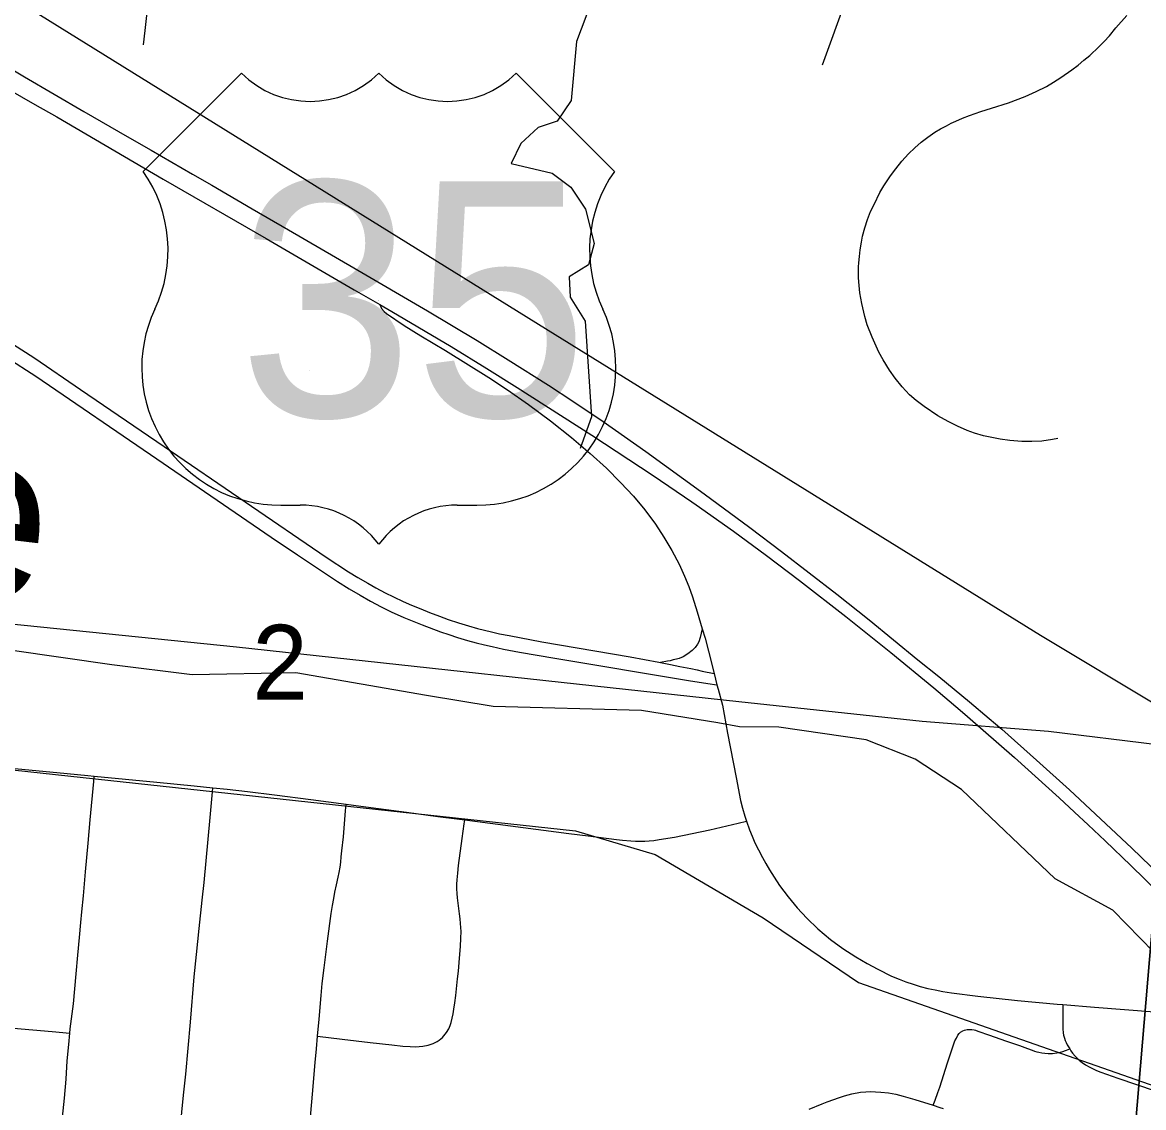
# Model space of a CAD drawing. Extents: x 0 to 34, y 0 to 22.
# Drawn here: x 5.11 to 5.737, y 17.523 to 18.131 of the extents above; entities that cross this region are included whole.
import ezdxf

# ---------------------------------------------------------------- set-up
doc = ezdxf.new("R2010")
doc.units = 0
for name, color, linetype in [('GM_X_City_Street', 7, 'Continuous'), ('GM_X_Corporation', 7, 'Continuous'), ('GM_X_Interchange_Ramps', 7, 'Continuous'), ('GM_X_Minor_River', 7, 'Continuous'), ('GM_X_Minor_River_Text', 7, 'Continuous'), ('GM_X_Rail_Line', 7, 'Continuous'), ('GM_X_Section_Text', 7, 'Continuous'), ('GM_X_State_Route', 7, 'Continuous'), ('GM_X_Township_Road', 7, 'Continuous'), ('GM_X_US_Location', 7, 'Continuous'), ('GM_X_US_Route', 7, 'Continuous'), ('GM_X_US_Shield', 7, 'Continuous')]:
    doc.layers.add(name, color=color, linetype=linetype)

msp = doc.modelspace()

# ---------------------------------------------------------------- linework, layer by layer
at = {"layer": 'GM_X_City_Street'}
for points in [[(5.55739, 18.1068), (5.57104, 18.14451), (5.57768, 18.1645), (5.5839, 18.18399), (5.58488, 18.1876), (5.58576, 18.19118), (5.58681, 18.19643), (5.58746, 18.20021), (5.5882, 18.20466), (5.58873, 18.20758), (5.58942, 18.21067), (5.59154, 18.21843), (5.59321, 18.22309), (5.5966, 18.23108), (5.60566, 18.25239), (5.60637, 18.25407)], [(5.1774, 18.11801), (5.17828, 18.126), (5.17939, 18.13614)], [(5.68919, 17.89762), (5.68616, 17.89706), (5.68007, 17.89623), (5.67456, 17.89593), (5.66903, 17.89602), (5.66228, 17.89655), (5.65679, 17.89733), (5.65222, 17.89821), (5.64758, 17.89914), (5.6424, 17.90065), (5.6384, 17.90213), (5.633, 17.90451), (5.62776, 17.90713), (5.62186, 17.91037), (5.61421, 17.91561), (5.60981, 17.91895), (5.60615, 17.92219), (5.60197, 17.92665), (5.59808, 17.93141), (5.59488, 17.93593), (5.5913, 17.94168), (5.58897, 17.946), (5.58512, 17.95442), (5.58248, 17.96133), (5.58101, 17.96601), (5.57935, 17.97321), (5.57837, 17.97928), (5.57767, 17.98537), (5.57753, 17.98776), (5.57747, 17.9912), (5.57757, 17.99368), (5.57773, 17.996), (5.57814, 17.99952), (5.57855, 18.00324), (5.57922, 18.00753), (5.57986, 18.01087), (5.58104, 18.0156), (5.58258, 18.02029), (5.58434, 18.02473), (5.58623, 18.02874), (5.5895, 18.03536), (5.59167, 18.03905), (5.59546, 18.04466), (5.59836, 18.04863), (5.60182, 18.05291), (5.60552, 18.05699), (5.60908, 18.06048), (5.61265, 18.06353), (5.61637, 18.06632), (5.62035, 18.06911), (5.62339, 18.07097), (5.6268, 18.07273), (5.62949, 18.07417), (5.63197, 18.07531), (5.63569, 18.07696), (5.63965, 18.07842), (5.64605, 18.08072), (5.65194, 18.08265), (5.66147, 18.08561), (5.67077, 18.0891), (5.67707, 18.09189), (5.6827, 18.09478), (5.68672, 18.09709), (5.69071, 18.09969), (5.69686, 18.10404), (5.70044, 18.10677), (5.70368, 18.1094), (5.70702, 18.11214), (5.7121, 18.1169), (5.71499, 18.11984), (5.71794, 18.1231), (5.72166, 18.12754), (5.72776, 18.13449)], [(5.13066, 17.50541), (5.13307, 17.52823), (5.13399, 17.53896), (5.13467, 17.54919), (5.13547, 17.55832), (5.13614, 17.56476), (5.1364, 17.56714), (5.13813, 17.58107), (5.13973, 17.59784), (5.14053, 17.60839), (5.14145, 17.61826), (5.14231, 17.62671), (5.14287, 17.63269), (5.14368, 17.64163), (5.14484, 17.65507), (5.14633, 17.6711), (5.14756, 17.68411), (5.14947, 17.70564), (5.14973, 17.70857)], [(5.19791, 17.51086), (5.19979, 17.53001), (5.20099, 17.54174), (5.2036, 17.57078), (5.20569, 17.59618), (5.20697, 17.60869), (5.20849, 17.62328), (5.21026, 17.63923), (5.21134, 17.64914), (5.21466, 17.6855), (5.21603, 17.69975), (5.21625, 17.70212)], [(5.27004, 17.50932), (5.2719, 17.5306), (5.27344, 17.5483), (5.27412, 17.55596), (5.27473, 17.56302), (5.27559, 17.57254), (5.27677, 17.58586), (5.27744, 17.59252), (5.27843, 17.60122), (5.28043, 17.61625), (5.28248, 17.63165), (5.28318, 17.63625), (5.28386, 17.64014), (5.28453, 17.64359), (5.28546, 17.64766), (5.28639, 17.65198), (5.28688, 17.65469), (5.28737, 17.65766), (5.2878, 17.66049), (5.28805, 17.66339), (5.28836, 17.66684), (5.28922, 17.67455), (5.29046, 17.68911), (5.29078, 17.69293)], [(5.27473, 17.56302), (5.28862, 17.56138), (5.30421, 17.55954), (5.31633, 17.55811), (5.32247, 17.55745), (5.32653, 17.55715), (5.32932, 17.55706), (5.33163, 17.55715), (5.33367, 17.55733), (5.33659, 17.55795), (5.33951, 17.55895), (5.34171, 17.56007), (5.34285, 17.56079), (5.34374, 17.56147), (5.34476, 17.56234), (5.34552, 17.56316), (5.34702, 17.56505), (5.34817, 17.56718), (5.34893, 17.56895), (5.34953, 17.57072), (5.35017, 17.57316), (5.3507, 17.57556), (5.35114, 17.57809), (5.35163, 17.58168), (5.35213, 17.58581), (5.3526, 17.58949), (5.35318, 17.59517), (5.35367, 17.59942), (5.35425, 17.60674), (5.35478, 17.61317), (5.35505, 17.61796), (5.35513, 17.62155), (5.35505, 17.62395), (5.35487, 17.62608), (5.35461, 17.62865), (5.35425, 17.63144), (5.3531, 17.64049), (5.35287, 17.64289), (5.35274, 17.64546), (5.35274, 17.64803), (5.35288, 17.65054), (5.35323, 17.65433), (5.35374, 17.65857), (5.35574, 17.67363), (5.35686, 17.68198), (5.35714, 17.6841)], [(5.69187, 17.58071), (5.69187, 17.57035), (5.69187, 17.56717), (5.69211, 17.56486), (5.69231, 17.56364), (5.69275, 17.56194), (5.69321, 17.56052), (5.69371, 17.55939), (5.6943, 17.55818), (5.69573, 17.55586), (5.69632, 17.55489), (5.69735, 17.55355), (5.69878, 17.5519), (5.69977, 17.55091), (5.70108, 17.54963), (5.70278, 17.54821), (5.70467, 17.54695), (5.70661, 17.5458), (5.70858, 17.54483), (5.71076, 17.54388), (5.71324, 17.54292), (5.72262, 17.53945), (5.76446, 17.52529)], [(5.0706, 17.57041), (5.08086, 17.56953), (5.10466, 17.56747), (5.12626, 17.56561), (5.13614, 17.56476)], [(5.61941, 17.52437), (5.62042, 17.52721), (5.62194, 17.53153), (5.623, 17.53453), (5.62739, 17.54809), (5.63087, 17.55866), (5.63154, 17.56044), (5.6323, 17.56198), (5.63319, 17.56357), (5.63393, 17.56448), (5.6347, 17.56519), (5.63602, 17.56603), (5.63678, 17.56635), (5.63757, 17.56658), (5.63837, 17.5667), (5.63921, 17.56678), (5.64019, 17.56676), (5.64096, 17.5667), (5.64224, 17.5665), (5.64298, 17.56629), (5.6444, 17.56587), (5.65079, 17.56363), (5.6599, 17.56046), (5.66771, 17.55775), (5.67209, 17.55615), (5.67479, 17.55514), (5.67599, 17.55471), (5.67729, 17.55433), (5.67856, 17.55399), (5.68007, 17.55373), (5.68186, 17.55351), (5.68367, 17.55337), (5.68604, 17.55337), (5.6886, 17.55365), (5.69143, 17.55433), (5.69398, 17.55515), (5.69573, 17.55586)], [(5.54988, 17.52211), (5.55725, 17.52522), (5.56009, 17.52631), (5.56684, 17.52875), (5.56971, 17.5297), (5.57381, 17.5308), (5.57859, 17.53164), (5.58161, 17.53194), (5.58402, 17.53201), (5.58706, 17.53194), (5.59009, 17.53172), (5.59427, 17.53124), (5.5984, 17.53049), (5.60254, 17.52949), (5.60903, 17.5276), (5.61941, 17.52437), (5.62309, 17.52316), (5.62499, 17.52246)]]:
    msp.add_lwpolyline(points, dxfattribs=at)
at = {"layer": 'GM_X_Corporation'}
for points in [[(4.80587, 18.33893), (5.79402, 18.23883), (5.70874, 17.23111), (4.7096, 17.33101)], [(5.79402, 18.23883), (6.80258, 18.13648), (6.71605, 17.12273), (5.70874, 17.23111)]]:
    msp.add_lwpolyline(points, close=True, dxfattribs=at)
at = {"layer": 'GM_X_Interchange_Ramps'}
for points in [[(5.30961, 17.97268), (5.31059, 17.9704), (5.31204, 17.96871), (5.3134, 17.96759), (5.32317, 17.96095), (5.33257, 17.95516), (5.34646, 17.94686), (5.3707, 17.93176), (5.38108, 17.92493), (5.39279, 17.91676), (5.40523, 17.90747), (5.41689, 17.89819), (5.42729, 17.88933), (5.43646, 17.88095), (5.44441, 17.8731), (5.45159, 17.86536), (5.45795, 17.85773), (5.46386, 17.84974), (5.46865, 17.84249), (5.47309, 17.83501), (5.47713, 17.82732), (5.48023, 17.82054), (5.48253, 17.81478), (5.48462, 17.80894), (5.48721, 17.80064), (5.49011, 17.7911), (5.49172, 17.78578), (5.4935, 17.77855), (5.49684, 17.76599)], [(5.49011, 17.7911), (5.48901, 17.78618), (5.48824, 17.78384), (5.48749, 17.78242), (5.48616, 17.78069), (5.4845, 17.77899), (5.4821, 17.77707), (5.47948, 17.77549), (5.47722, 17.77455), (5.47562, 17.77403), (5.47388, 17.77365), (5.47218, 17.77323), (5.47058, 17.77295), (5.46674, 17.77227)]]:
    msp.add_lwpolyline(points, dxfattribs=at)
at = {"layer": 'GM_X_Minor_River'}
for points in [[(5.42804, 18.14215), (5.41965, 18.11992), (5.41675, 18.08695), (5.40894, 18.07535), (5.39825, 18.07178), (5.3886, 18.06288), (5.38307, 18.05161), (5.40611, 18.04616), (5.41658, 18.03834), (5.42469, 18.026), (5.42964, 18.0069), (5.42637, 17.99482), (5.41563, 17.98822), (5.41617, 17.97681), (5.42464, 17.96334), (5.42817, 17.90971), (5.42176, 17.892)], [(5.75044, 17.60215), (5.71994, 17.63359), (5.68764, 17.65102), (5.63511, 17.70118), (5.60926, 17.71808), (5.58177, 17.72894), (5.53297, 17.7361), (5.51097, 17.7362), (5.49888, 17.73837), (5.45614, 17.74539), (5.37311, 17.7476), (5.33567, 17.75374), (5.2627, 17.76636), (5.20464, 17.76536), (5.1596, 17.77091), (5.04648, 17.78707)]]:
    msp.add_lwpolyline(points, dxfattribs=at)
at = {"layer": 'GM_X_Rail_Line'}
for points in [[(3.83258, 18.78915), (4.04668, 18.71724), (4.20013, 18.66068), (4.27929, 18.62258), (4.42905, 18.54243), (4.65516, 18.4157), (4.85706, 18.2978), (5.4078, 17.95591), (5.67948, 17.78757), (5.87786, 17.66832)], [(3.75111, 17.91984), (4.13437, 17.89482), (4.75572, 17.82927), (5.22932, 17.78106), (5.51048, 17.75031), (5.61322, 17.7394), (5.68379, 17.7337), (5.74481, 17.72625), (5.77844, 17.71835), (5.81904, 17.69829), (5.87786, 17.66832)], [(3.70448, 17.42229), (3.8238, 17.40968), (4.1793, 17.59433), (4.21884, 17.60563), (4.53197, 17.66904), (4.631, 17.71273), (4.67602, 17.72967), (4.74678, 17.74703), (4.82147, 17.74282), (5.41919, 17.67801), (5.46375, 17.66473), (5.52417, 17.62929), (5.5775, 17.59308), (5.86559, 17.49221), (5.95124, 17.46244), (5.99921, 17.4478), (6.04755, 17.44691), (6.14412, 17.48501), (6.16189, 17.48329), (6.20118, 17.45896), (6.42917, 17.31711), (7.48054, 16.67263)]]:
    msp.add_lwpolyline(points, dxfattribs=at)
at = {"layer": 'GM_X_State_Route'}
for points in [[(5.10406, 17.95071), (5.11653, 17.94259), (5.14213, 17.92504), (5.18883, 17.89321), (5.27961, 17.83121), (5.29211, 17.82302), (5.29727, 17.81982), (5.30282, 17.81666), (5.30746, 17.81407), (5.31269, 17.81133), (5.31733, 17.80897), (5.32278, 17.80642), (5.32736, 17.80437), (5.3325, 17.80219), (5.33739, 17.80026), (5.34296, 17.79815), (5.34783, 17.7964), (5.35357, 17.79453), (5.35925, 17.79278), (5.36434, 17.79134), (5.36813, 17.79031), (5.37219, 17.78935), (5.3766, 17.78834), (5.38193, 17.78726), (5.40028, 17.78389), (5.44976, 17.77535), (5.4657, 17.77247), (5.46674, 17.77227), (5.47228, 17.77116), (5.47762, 17.77001), (5.48371, 17.76878), (5.48716, 17.76804), (5.48995, 17.76738), (5.49684, 17.76599), (5.4983, 17.75964)], [(5.10088, 17.94305), (5.11701, 17.93248), (5.18482, 17.88631), (5.24884, 17.84248), (5.26346, 17.83253), (5.286, 17.8176), (5.29249, 17.81348), (5.29858, 17.80987), (5.30433, 17.80666), (5.31033, 17.80345), (5.31601, 17.80058), (5.32307, 17.79737), (5.33327, 17.79326), (5.3435, 17.78948), (5.34819, 17.78784), (5.35316, 17.78628), (5.35867, 17.78463), (5.36352, 17.78332), (5.36828, 17.78209), (5.37256, 17.7811), (5.37881, 17.77978), (5.38789, 17.77797), (5.40758, 17.7746), (5.48247, 17.76219), (5.49315, 17.76047), (5.4983, 17.75964)], [(5.4983, 17.75964), (5.49902, 17.75724), (5.5014, 17.74843), (5.50431, 17.73261), (5.50905, 17.70778), (5.51154, 17.69488), (5.51269, 17.6906), (5.51393, 17.68625), (5.51488, 17.68337), (5.51657, 17.6786), (5.51795, 17.67498), (5.51959, 17.67128), (5.52149, 17.66742), (5.52373, 17.66308), (5.52559, 17.65969), (5.52772, 17.65617), (5.53037, 17.65196), (5.53341, 17.64739), (5.53812, 17.64095), (5.54315, 17.63478), (5.54863, 17.62902), (5.55487, 17.62313), (5.56193, 17.61721), (5.56883, 17.61209), (5.57602, 17.60739), (5.5824, 17.6037), (5.58834, 17.60045), (5.59608, 17.59669), (5.60032, 17.59492), (5.60401, 17.59344), (5.60821, 17.59204), (5.61214, 17.59086), (5.61643, 17.58974), (5.62048, 17.58888), (5.62481, 17.58801), (5.62956, 17.58728), (5.64428, 17.58544), (5.66651, 17.58307), (5.68876, 17.58095), (5.69187, 17.58071), (5.70965, 17.5793), (5.74319, 17.57657)]]:
    msp.add_lwpolyline(points, dxfattribs=at)
at = {"layer": 'GM_X_Township_Road'}
for points in [[(5.0392, 17.71886), (5.07616, 17.71549), (5.09943, 17.71336), (5.12886, 17.71056), (5.14612, 17.70891), (5.14973, 17.70857)], [(5.14973, 17.70857), (5.18484, 17.70522), (5.20579, 17.70316), (5.21625, 17.70212)], [(5.21625, 17.70212), (5.22417, 17.70133), (5.23547, 17.70004), (5.2507, 17.6982), (5.27104, 17.69558), (5.29078, 17.69293)], [(5.29078, 17.69293), (5.30183, 17.69145), (5.32457, 17.68836), (5.34209, 17.68607), (5.35278, 17.68467), (5.35714, 17.6841)], [(5.35714, 17.6841), (5.41533, 17.67653), (5.42622, 17.67512)], [(5.42622, 17.67512), (5.44207, 17.67308), (5.44541, 17.67274), (5.45007, 17.6724), (5.45273, 17.67225), (5.4556, 17.67225), (5.45791, 17.67225), (5.46046, 17.67242), (5.463, 17.67266), (5.46601, 17.67304), (5.47454, 17.67443), (5.49424, 17.67858), (5.51019, 17.68228), (5.51488, 17.68337)]]:
    msp.add_lwpolyline(points, dxfattribs=at)
at = {"layer": 'GM_X_US_Route'}
for points in [[(4.8155, 18.25643), (4.82068, 18.25354), (4.85622, 18.23305), (4.88634, 18.21564), (4.92724, 18.19206), (4.99919, 18.15145), (5.05693, 18.11854), (5.0878, 18.10117), (5.11657, 18.08468)], [(5.07712, 18.12027), (5.11072, 18.10018), (5.14396, 18.08069), (5.16822, 18.06677), (5.1817, 18.05905), (5.20477, 18.04559), (5.21555, 18.0394), (5.23811, 18.02629), (5.2585, 18.0144), (5.29504, 17.99318), (5.33636, 17.96906), (5.36412, 17.95255), (5.38155, 17.94177), (5.40411, 17.92747), (5.41763, 17.91864), (5.43457, 17.90713), (5.45844, 17.89032), (5.49119, 17.8667), (5.51668, 17.84788), (5.53452, 17.83441), (5.56549, 17.81049), (5.58347, 17.79621), (5.61082, 17.7737), (5.62241, 17.76431), (5.63971, 17.75015), (5.65064, 17.74086), (5.65769, 17.73487), (5.67723, 17.71761), (5.69557, 17.70085), (5.73052, 17.66819), (5.74618, 17.65314)], [(5.11657, 18.08468), (5.12878, 18.07768), (5.18829, 18.04283), (5.24592, 18.00966), (5.29534, 17.98094), (5.30961, 17.97268), (5.31632, 17.9688), (5.3495, 17.94918), (5.36961, 17.93679), (5.38642, 17.92616), (5.42835, 17.89944), (5.46262, 17.87689), (5.48427, 17.86213)], [(5.48427, 17.86213), (5.48676, 17.86042), (5.50756, 17.84568), (5.5261, 17.83205), (5.54444, 17.81818), (5.57046, 17.79798), (5.59568, 17.77777), (5.61974, 17.75809), (5.63441, 17.74559), (5.63855, 17.74196), (5.66481, 17.71897), (5.68977, 17.69653), (5.69845, 17.68852), (5.70614, 17.68127), (5.71567, 17.67237), (5.73003, 17.65861), (5.75314, 17.63603), (5.77612, 17.61335), (5.79557, 17.59413), (5.80438, 17.58536), (5.81284, 17.57696)]]:
    msp.add_lwpolyline(points, dxfattribs=at)
at = {"layer": 'GM_X_US_Shield'}
for p, q in [((5.23215, 18.10211), (5.17722, 18.04717)), ((5.44089, 18.04717), (5.38596, 18.10211)), ((5.25413, 17.86041), (5.26511, 17.86041)), ((5.353, 17.86041), (5.36399, 17.86041))]:
    msp.add_line(p, q, dxfattribs=at)
for centre, radius, start, end in [((5.2706, 18.14134), 0.05493, 225.573, 314.427), ((5.34751, 18.14134), 0.05493, 225.573, 314.427), ((5.11423, 18.00306), 0.0769, 334.54712, 35.00093), ((5.50389, 18.00306), 0.0769, 144.99907, 205.45288), ((5.25327, 17.93731), 0.0769, 154.83192, 270.63826), ((5.36485, 17.93731), 0.0769, 269.36174, 25.16808), ((5.26511, 17.80547), 0.05493, 36.8699, 90), ((5.353, 17.80547), 0.05493, 90, 143.1301)]:
    msp.add_arc(centre, radius, start, end, dxfattribs=at)

# ---------------------------------------------------------------- texts
at = {"layer": 'GM_X_Minor_River_Text'}
msp.add_text('Little', height=0.094696, rotation=353.16845, dxfattribs=at).set_placement((4.85434, 17.83659))
at = {"layer": 'GM_X_Section_Text'}
msp.add_text('2', height=0.04186, rotation=0.00001, dxfattribs=at).set_placement((5.23823, 17.75144))
at = {"layer": 'GM_X_US_Location'}
for s, p in [('0', (5.30898, 17.97472)), ('/', (5.309, 17.97472))]:
    msp.add_text(s, height=0.000189, dxfattribs=at).set_placement(p)
msp.add_text('35', height=0.000189, rotation=0.00001, dxfattribs=at).set_placement((5.26989, 17.93552))
at = {"layer": 'GM_X_US_Shield'}
msp.add_text('35', height=0.131836, dxfattribs=at).set_placement((5.23043, 17.90985))

doc.saveas('drawing.dxf')
